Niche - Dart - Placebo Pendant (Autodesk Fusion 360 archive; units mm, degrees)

design "Dart - Modular" references "Modular - Placedo - Cord Set", "Modular - Placebo - Bayonet Connector"
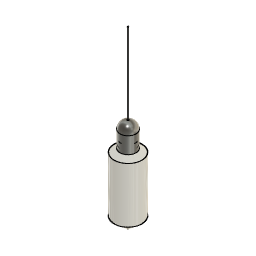
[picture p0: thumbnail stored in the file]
sketch "Sketch1" plane through (0, 0, 0) normal (0, 1, 0) x axis (1, 0, 0)
  line L1 (0, 88.9) -> (0, -114.3)
  line L2 (76.2, 0) -> (-76.2, 0)
  line L3 (26.9875, 88.9) -> (26.9875, -114.3)
  line L4 (-26.9875, 88.9) -> (-26.9875, -114.3)
  point P6 (26.9875, -114.3)
  point P8 (-26.9875, -114.3)
  point P7 (26.9875, 88.9)
  point P9 (-26.9875, 88.9)
  vertical L1
  perpendicular L1 L2
  symmetric L1 P6 P8
  symmetric L1 P7 P9
  dimension "d1" = 26.9875
derived_base_feature "Derived Base Feature" bodies "Body1", "Dart Modular"
sketch "Sketch2" plane through (0, 0, 0) normal (0, 1, 0) x axis (1, 0, 0)
  line L1 (27.1179, -114.2701) -> (27.14, -126.9701)
  line L2 (-27.3126, -134.4744) -> (-27.2907, -121.7744)
  line L3 (42.7904, -104.4452) -> (27.1179, -114.2701)
  line L4 (-27.2907, -121.7744) -> (-50.8, -109.2129)
  line L5 (42.806, 93.0737) -> (42.7904, -104.4452)
  line L6 (-50.8, -109.2129) -> (-50.8, 90.6517)
  line L7 (-0.5764, 133.2744) -> (42.806, 93.0737)
  line L8 (-50.8, 90.6517) -> (-0.5764, 133.2744)
  line L9 (27.0943, -134.3794) -> (-27.3126, -134.4744)
  line L10 (-0.5764, 133.2744) -> (-0.1091, -134.4269)
  line L11 (-49.53, 90.0638) -> (0.2269, 132.2904)
  line L12 (-49.53, -108.4516) -> (-49.53, 90.0638)
  line L13 (-26.0194, -121.0138) -> (-49.53, -108.4516)
  line L14 (-26.0426, -134.4722) -> (-26.0194, -121.0138)
  line L15 (0, 88.9) -> (0, -114.3)
  point P8 (-0.1091, -134.4269)
  point P19 (-26.0426, -134.4722)
  point P2 (27.14, -126.9701)
  point P3 (27.1179, -114.2701)
  point P4 (-27.2907, -121.7744)
  point P5 (-27.3126, -134.4744)
  perpendicular L1 L9
  midpoint L9 P8
  perpendicular L9 L10
  coincident L9 P19
  dimension "d6" distance P2 P3 = 12.7
  dimension "d7" distance P4 P5 = 12.7
  dimension "d8" distance L6 L15 = 50.8
remove_body "RemoveBody1"
revolve "Revolve1" sketch "Sketch2" AlongAngle 360 bodies "Dart Modular"
component_from_bodies "Body->Comp"
component_insert "Component Insert1" bodies "Dart Modular"
component_insert "Component Insert2" bodies "Dart Modular"
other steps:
base_feature "Base Feature" bodies "Dart Modular"
create_component "CreateComponent1"
remove_body "RemoveBody2"
named bodies: "Body1", "Dart Modular"

design "Modular - Placebo - Bayonet Connector"
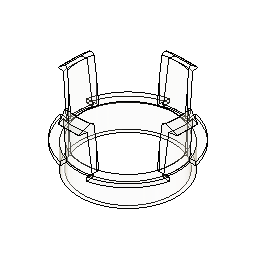
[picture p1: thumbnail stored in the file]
sketch "Sketch1" plane through (0, 0, 0) normal (0, 0, 1) x axis (1, 0, 0)
  circle C1 centre (0, 0) radius 23.241
  point P1 (0, 0)
  point P2 (0, 0)
  coincident P1 P2
  dimension "d1" diameter C1 = 46.482
extrude "Extrude1" new body sketch "Sketch1" along normal blind 11.176
sketch "Sketch2" plane through (0, 0, 11.176) normal (0, 0, 1) x axis (-1, 0, 0)
  line L1 (-23.2795, -6.35) -> (-26.1645, -6.35)
  line L2 (-23.2795, 6.35) -> (-26.1645, 6.35)
  line L3 (26.1645, -6.35) -> (23.2795, -6.35)
  line L4 (26.1645, 6.35) -> (23.2795, 6.35)
  line L5 (6.35, -23.2795) -> (6.35, -26.1645)
  line L6 (-6.35, -23.2795) -> (-6.35, -26.1645)
  line L7 (6.35, 26.1645) -> (6.35, 23.2795)
  line L8 (-6.35, 26.1645) -> (-6.35, 23.2795)
  line L9 (0, -24.13) -> (0, -26.924)
  line L10 (6.35, -23.2795) -> (6.35, -22.3567)
  line L11 (-6.35, -23.2795) -> (-6.35, -22.3567)
  line L12 (23.2795, -6.35) -> (22.3567, -6.35)
  line L13 (23.2795, 6.35) -> (22.3567, 6.35)
  line L14 (-23.2795, 6.35) -> (-22.3567, 6.35)
  line L15 (-23.2795, -6.35) -> (-22.3567, -6.35)
  line L16 (6.35, 22.3567) -> (6.35, 23.2795)
  line L17 (-6.35, 22.3567) -> (-6.35, 23.2795)
  circle C1 centre (0, 0) radius 23.241
  arc A1 centre (0, 0) radius 26.924 clockwise from (-6.35, -26.1645) to (-26.1645, -6.35)
  arc A2 centre (0, 0) radius 26.924 clockwise from (26.1645, -6.35) to (6.35, -26.1645)
  arc A3 centre (0, 0) radius 24.13 clockwise from (23.2795, 6.35) to (23.2795, -6.35)
  arc A4 centre (0, 0) radius 24.13 clockwise from (6.35, -23.2795) to (-6.35, -23.2795)
  arc A5 centre (0, 0) radius 26.924 clockwise from (6.35, 26.1645) to (26.1645, 6.35)
  arc A6 centre (0, 0) radius 26.924 clockwise from (-26.1645, 6.35) to (-6.35, 26.1645)
  arc A7 centre (0, 0) radius 24.13 clockwise from (-6.35, 23.2795) to (6.35, 23.2795)
  arc A8 centre (0, 0) radius 24.13 clockwise from (-23.2795, -6.35) to (-23.2795, 6.35)
  point P2 (0, 0)
  point P4 (0, 0)
  point P12 (-23.2795, -6.35)
  point P13 (-22.3567, -6.35)
  point P14 (-23.2795, 6.35)
  point P15 (-22.3567, 6.35)
  point P16 (22.3567, -6.35)
  point P18 (22.3567, 6.35)
  point P24 (6.35, 23.2795)
  point P28 (6.35, -22.3567)
  point P29 (-6.35, -22.3567)
  point P31 (-6.35, 26.1645)
  point P35 (0, -24.13)
  point P36 (6.35, 22.3567)
  point P37 (-6.35, 22.3567)
  coincident P2 P4
  vertical L9
  concentric A2 A3
  concentric A1 A2
  coincident P12 A3
  coincident C1 P13
  coincident P14 A3
  coincident C1 P15
  coincident C1 P16
  coincident C1 P18
  concentric A2 A5
  coincident P24 L5
  concentric A3 A7
  concentric A4 A7
  coincident C1 P28
  coincident C1 P29
  coincident P31 A5
  concentric A5 A6
  concentric A7 A8
  coincident A4 P35
  horizontal L12
  coincident C1 P36
  parallel L7 L16
  coincident C1 P37
  parallel L8 L17
  dimension "d4" diameter A2 = 53.848
extrude "Extrude2" add sketch "Sketch2" profile of C1 A8 L10 L11 L12 L13 L14 L15 L16 L17 along normal blind 0.762
extrude "Extrude3" add sketch "Sketch2" profile of C1 A6 L7 L8 L4 L3 L10 L11 L12 L13 L14 L15 L16 L17 along normal blind 1.7018
extrude "Extrude4" add sketch "Sketch2" profile of C1 along normal blind 1.7018
work_plane "WorkPlane1" AlongDistance 33.8963
sketch "Sketch3" plane through (0, 0, 33.8963) normal (0, 0, 1) x axis (1, 0, 0)
  line L1 (0, 20.3925) -> (0, 27.5045)
  line L2 (-6.604, 20.3925) -> (-6.604, 27.5045)
  line L3 (6.604, 20.3925) -> (6.604, 27.5045)
  circle C1 centre (0, 0) radius 23.7363
  circle C2 centre (0, 0) radius 27.305
  arc A1 centre (0.0021, 0.2001) radius 23.9364 clockwise from (-6.604, 23.2068) to (6.604, 23.208)
  arc A2 centre (0.0021, 0.2001) radius 21.3964 clockwise from (-6.604, 20.5511) to (6.604, 20.5525)
  point P1 (0, 0)
  point P2 (0, 0)
  point P6 (-6.604, 27.5045)
  point P8 (6.604, 27.5045)
  point P7 (-6.604, 20.3925)
  point P9 (6.604, 20.3925)
  point P11 (-6.604, 23.2068)
  point P12 (6.604, 23.208)
  point P14 (-6.604, 20.5511)
  point P15 (6.604, 20.5525)
  coincident P1 P2
  concentric C1 C2
  vertical L1
  symmetric L1 P6 P8
  symmetric L1 P7 P9
  tangent C1 A1
  coincident L2 P11
  coincident L3 P12
  concentric A1 A2
  coincident L2 P14
  coincident L3 P15
  dimension "d14" diameter C1 = 47.4726
  dimension "d15" diameter C2 = 54.61
  dimension "d16" = 6.604
extrude "Extrude5" new body sketch "Sketch3" profile of C1 L1 L2 L3 A1 A2 against normal blind 21.59
sketch "Sketch4" plane through (0, 0, 33.8963) normal (0, 0, 1) x axis (-1, 0, 0)
  line L1 (6.604, -20.5511) -> (6.604, -23.2068)
  line L2 (-6.604, -23.208) -> (-6.604, -20.5525)
  line L3 (-5.08, -26.67) -> (-6.604, -20.5525)
  line L4 (5.08, -26.67) -> (-5.08, -26.67)
  line L5 (6.604, -20.5511) -> (5.08, -26.67)
  arc A1 centre (-0.0021, -0.2001) radius 23.9364 clockwise from (6.604, -23.2068) to (-6.604, -23.208)
  arc A2 centre (-0.0021, -0.2001) radius 21.3964 clockwise from (6.604, -20.5511) to (-6.604, -20.5525)
  point P6 (-6.604, -20.5525)
  point P7 (-6.604, -20.5525)
  point P5 (6.604, -20.5511)
  point P10 (6.604, -20.5511)
  coincident P6 P7
  perpendicular L2 L4
  coincident P5 P10
extrude "Extrude6" add sketch "Sketch4" profile of A1 A2 L3 L4 L5 against normal blind 3.175
move "Move1"
sketch "Sketch5" plane through (0, 3.4565, 35.8974) normal (0, 0.0958, 0.9954) x axis (-1, 0, 0)
  line L1 (6.604, -19.277) -> (6.604, -21.9327)
  line L2 (-6.604, -21.9339) -> (-6.604, -19.2784)
  line L3 (-5.08, -25.3959) -> (-5.8947, -22.1257)
  line L4 (5.08, -25.3959) -> (-5.08, -25.3959)
  line L5 (5.8948, -22.1246) -> (5.08, -25.3959)
  line L6 (-8.1218, -17.3223) -> (-6.0831, -25.506)
  line L7 (-0.004, -17.3223) -> (-0.0002, -17.3223)
  line L8 (-8.1218, -17.3223) -> (-6.8295, -17.3223)
  line L9 (0, -25.3959) -> (0.0001, -20.3223)
  line L10 (-6.8295, -17.3223) -> (-4.7917, -25.5025)
  line L11 (8.1222, -17.3227) -> (6.0831, -25.5062)
  line L12 (8.1222, -17.3227) -> (6.8299, -17.3226)
  line L13 (-4.7917, -25.5025) -> (-6.1096, -25.506)
  line L14 (4.7917, -25.5027) -> (6.0831, -25.5062)
  line L15 (6.8299, -17.3226) -> (4.7917, -25.5027)
  arc A1 centre (-0.0021, 1.074) radius 23.9364 clockwise from (6.604, -21.9327) to (5.8948, -22.1246)
  arc A2 centre (-0.0021, 1.074) radius 21.3964 clockwise from (6.604, -19.277) to (-6.604, -19.2784)
  arc A3 centre (-0.0021, 1.074) radius 23.9364 clockwise from (-5.8947, -22.1257) to (-6.604, -21.9339)
  arc A4 centre (-0.0021, 1.074) radius 18.3964 clockwise from (5.6778, -16.4236) to (-5.6783, -16.4247)
  point P14 (-0.0002, -17.3223)
  point P15 (-8.1218, -17.3223)
  point P16 (-0.004, -17.3223)
  point P17 (0.0001, -20.3223)
  point P18 (0, -25.3959)
  point P20 (8.1222, -17.3227)
  point P19 (-6.8295, -17.3223)
  point P21 (6.8299, -17.3226)
  point P23 (-6.0831, -25.506)
  point P26 (6.8299, -17.3226)
  point P24 (-4.7917, -25.5025)
  point P25 (4.7917, -25.5027)
  midpoint A4 P14
  horizontal L7
  coincident P15 L7
  coincident A4 P16
  collinear L7 L8
  midpoint A2 P17
  midpoint L4 P18
  symmetric P15 L9 P20
  symmetric L9 P19 P21
  coincident L13 P23
  symmetric L9 P19 P26
  symmetric L9 P24 P25
  dimension "d22" = -3
extrude "Extrude7" cut sketch "Sketch5" profile of A1 L1 A2 L2 A3 L3 L4 L5 L8 L6 L10 L11 L12 L13 L14 L15 against normal blind 25.146 taper -1.45
remove_body "RemoveBody1"
remove_body "RemoveBody2"
chamfer "Chamfer1" sketch "Sketch4" distance 4.572 distance 3.048
circular_pattern "C-Pattern1" TotalAngle 360
extrude "Extrude8" add sketch "Sketch4" along a picked direction blind 0.508
extrude "Extrude9" add of existing geometry blind 0.508
extrude "Extrude10" add of existing geometry blind 0.508
extrude "Extrude11" add of existing geometry blind 0.508
hole "Hole1" sketch "Sketch4" HoleDepth 38.1 HoleDiameter 42.926 TipAngle 118
fillet "Fillet1" sketch "Sketch4" radius 1.27

design "Modular - Placedo - Cord Set"
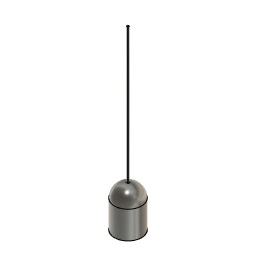
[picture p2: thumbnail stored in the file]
sketch "Sketch1" plane through (0, 0, 0) normal (0, 1, 0) x axis (1, 0, 0)
  line L1 (0, -88.9) -> (0, 0)
  line L2 (-29.5402, -88.9) -> (-29.5402, 0)
  line L3 (29.5402, -88.9) -> (29.5402, 0)
  line L4 (29.5402, 8.5598) -> (29.5402, -59.3598)
  line L5 (-29.5402, -59.3598) -> (-29.5402, 8.5598)
  line L6 (0, 38.1) -> (0, -88.9)
  line L7 (29.5402, 0) -> (-29.5402, 0)
  arc A1 centre (0, 8.5598) radius 29.5402 clockwise from (-29.5402, 8.5598) to (29.5402, 8.5598)
  arc A2 centre (0, -59.3598) radius 29.5402 clockwise from (29.5402, -59.3598) to (-29.5402, -59.3598)
  point P1 (0, 0)
  point P2 (0, 0)
  point P4 (-29.5402, 0)
  point P6 (29.5402, 0)
  point P5 (-29.5402, -88.9)
  point P7 (29.5402, -88.9)
  point P3 (0, -88.9)
  point P14 (0, 38.1)
  coincident P1 P2
  vertical L1
  symmetric L1 P4 P6
  symmetric L1 P5 P7
  tangent L4 A1
  tangent A1 L5
  parallel L4 L5
  tangent L5 A2
  tangent L4 A2
  midpoint P3 A2
  midpoint A1 P14
  parallel L1 L6
  dimension "d1" = 29.5402
revolve "Revolve1" sketch "Sketch1" AlongAngle 360
shell "Shell1" innerThickness 1.524
sketch "Sketch2" plane through (0, 0, 0) normal (0, 0, 1) x axis (1, 0, 0)
  circle C1 centre (0, 0) radius 2.8575
  point P1 (0, 0)
  point P2 (0, 0)
  coincident P1 P2
  dimension "d4" diameter C1 = 5.715
extrude "Extrude1" cut sketch "Sketch2" along normal blind 101.6
sketch "Sketch3" plane through (0, 0, 0) normal (0, 0, 1) x axis (1, 0, 0)
  circle C1 centre (0, 0) radius 2.286
  point P1 (0, 0)
  point P2 (0, 0)
  coincident P1 P2
  dimension "d7" diameter C1 = 4.572
extrude "Extrude2" new body sketch "Sketch3" along normal blind 304.8
move "Move1"
sketch "Sketch4" plane through (0, 0, 0) normal (0, 0, 1) x axis (1, 0, 0)
  circle C1 centre (0, 0) radius 18.796
  point P1 (0, 0)
  point P2 (0, 0)
  coincident P1 P2
  dimension "d10" diameter C1 = 37.592
extrude "Extrude3" new body sketch "Sketch4" along normal blind 31.75
move "Move2"
offset_faces "OffsetFaces1" distance 38.1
